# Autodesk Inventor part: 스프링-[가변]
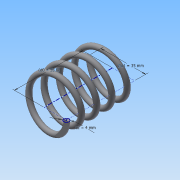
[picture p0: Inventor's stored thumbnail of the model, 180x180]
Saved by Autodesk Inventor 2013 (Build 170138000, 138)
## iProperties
Created: 2015-04
Part Number: 스프링-[가변]
Material: 일반
Document SubType Name: Modeling
Designer: Administrator
Density: 1 g/cm^3
Author: Administrator
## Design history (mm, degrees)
sketch "스케치1"
  geometry: L1 (0, 0)-(17.5, 0); L2 (17.5, 0)-(17.5, 53.5); L3 (17.5, 53.5)-(0, 53.5); L4 (0, 53.5)-(0, 0); C1 r 2 at (17.5, 0)
  constraints: 8 end point, 2 parallel, 1 centre point, 1 coincident, 1 horizontal, 1 perpendicular
  dimensions: "d0" = 53.5 distance of L3.end L1.start (derived); "d1" = 35 diameter of L2 L4; "d2" = 4 diameter of C1
feature "코일1" sketch "스케치1" pitch "d3" = 10; turns "d5" = 4.5; dims "d4" = 53.5 (= d0), "d6" = 0, angle "d7" = 90 deg, angle "d8" = 90 deg, "d9" = 0, "d10" = 0
sketch "스케치2"
  geometry: L1 (-19.5, 0)-(-15.5, 0) reference; 1 further point
  constraints: 1 horizontal alignment
extrude "돌출1" cut sketch "스케치2" distance "d11" = 10; taper "d12" = 0 deg
node "작업 평면1"
sketch "스케치3"
  geometry: L1 (15.5, 0)-(19.5, 0) reference; 1 further point
  constraints: 1 horizontal alignment
extrude "돌출2" cut sketch "스케치3" distance "d14" = 10; taper "d15" = 0 deg
node "솔리드1"
node "절단 모서리 투영1"
node "절단 모서리 투영2"
other parameters: "d13" = 53.5 (= d0)
